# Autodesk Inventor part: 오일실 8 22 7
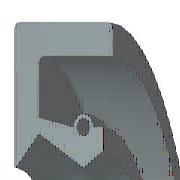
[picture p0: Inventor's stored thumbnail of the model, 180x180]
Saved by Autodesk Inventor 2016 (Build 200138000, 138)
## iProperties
IsCustomPart: 1
Created: 2012-02
Part Number: 오일실 8 22 7
Material: 고무
Description: 오일-실
Document SubType Name: Modeling
Standard: KS B 2804
Designer: mduedu
Standards Organization: KS
Language: ko-KR
Size Designation: D - 8 22 7
Categories: <MemberInstance><Categories><Category DisplayName="샤프트 부품" InternalName="7f7aeb1f-a693-4053-b835-cee3144e0d98" Mnemonic="SHFT"><Category DisplayName="실링" Intern
Density: 0.93 g/cm^3
Appearance: 고무 - 검은색 - 버전 1.1
Mass: 1.28441 g
Surface Area: 18.2787 cm^2
Volume: 1.38108 cm^3
Author: mduedu
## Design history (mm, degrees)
revolve "본체" stored, may be unused: angle "d17" = 90 deg
revolve "스프링1" stored, may be unused: angle "d18" = 90 deg
body "Solid1"
sketch "스케치1"
  geometry: L1 (0, 11)-(7, 11); L2 (7, 9.25)-(1.75, 9.25); L3 (1.75, 5.75)-(4.9, 4); L4 (4.9, 4)-(0, 4); L5 (0, 0)-(9.586, 0) reference; L6 (4.9, 4)-(6.3, 4.875); L7 (0, 18)-(0, -3) reference; L8 (-1.941, 0)-(11.507, 0) reference; L9 (4.2, 6.1)-(1.75, 6.59); L10 (1.75, 6.59)-(1.75, 9.25); L11 (0, 11)-(0, 4.088); L12 (4.9, 4)-(0, 4); L13 (1.75, 5.75)-(0.152, 4.028); L14 (7, 11)-(7, 9.25); L15 (5.6, 6.1)-(6.3, 6.1); L16 (6.3, 6.1)-(6.3, 4.875); C1 r 0.455 at (4.9, 6.1); A1 r 0.7 centre (4.9, 6.1) between (5.6, 6.1) and (4.2, 6.1); A2 r 0.088 centre (0.088, 4.088) between (0, 4.088) and (0.152, 4.028); 1 further point
  constraints: 28 end point, 5 horizontal alignment, 5 point on line, 4 point on circle, 4 vertical alignment, 3 centre point, 3 tangent, 2 collinear, 2 horizontal, 2 perpendicular, 1 coincident, 1 parallel
  dimensions: "d0" = 22 diameter of L1 L5 (= SD2); "d1" = 1.75 distance of L1.end L2.start (= SD); "d2" = 0.91 diameter of C1 (= SPDI); "d3" = 1.4 diameter of A1 (= SPDA); "d4" = 8 diameter of L3.end L5 (= NND); "d5" = 11.5 diameter of L3.start L5 (= TKDM); "d7" = 13.18 diameter of L9.end L5 (= TKDM + 0.24 x SWDT); "d8" = 1.75 distance between parallel lines of L11 L10 (= SD); "d9" = 4.9 distance from line of L11 C1.centre (= SPDST); "d10" = 12.2 diameter of C1.centre L5 (= HLDM); "d11" = 0.0875 radius of A2 (= 0.25 x LAB); "d12" = 6.3 distance between parallel lines of L11 L16 (= SDI); "d13" = 9.75 diameter of L6.end L5 (= ABDM); "d14" = 7 distance from line of L11 L1.end (= SWDT)
fillet "모깎기1" dims "d6" = 0.3 (= RR)
other parameters: "SD2" = 22 [user parameter; used in 1 equation term], "SWDT" = 7 [user parameter; used in 2 equation terms], "RR" = 0.3 [user parameter; used in 1 equation term], "SD" = 1.75 [user parameter; used in 2 equation terms], "NND" = 8 [user parameter; used in 1 equation term], "SPDA" = 1.4 [user parameter; used in 1 equation term], "SPDI" = 0.91 [user parameter; used in 1 equation term], "TKDM" = 11.5 [user parameter; used in 2 equation terms], "HLDM" = 12.2 [user parameter; used in 1 equation term], "ABDM" = 9.75 [user parameter; used in 1 equation term], "SDI" = 6.3 [user parameter; used in 1 equation term], "SPDST" = 4.9 [user parameter; used in 1 equation term], "LAB" = 0.35 [user parameter; used in 1 equation term], "d15" = 0, "d16" = 0, "d19" = 0
